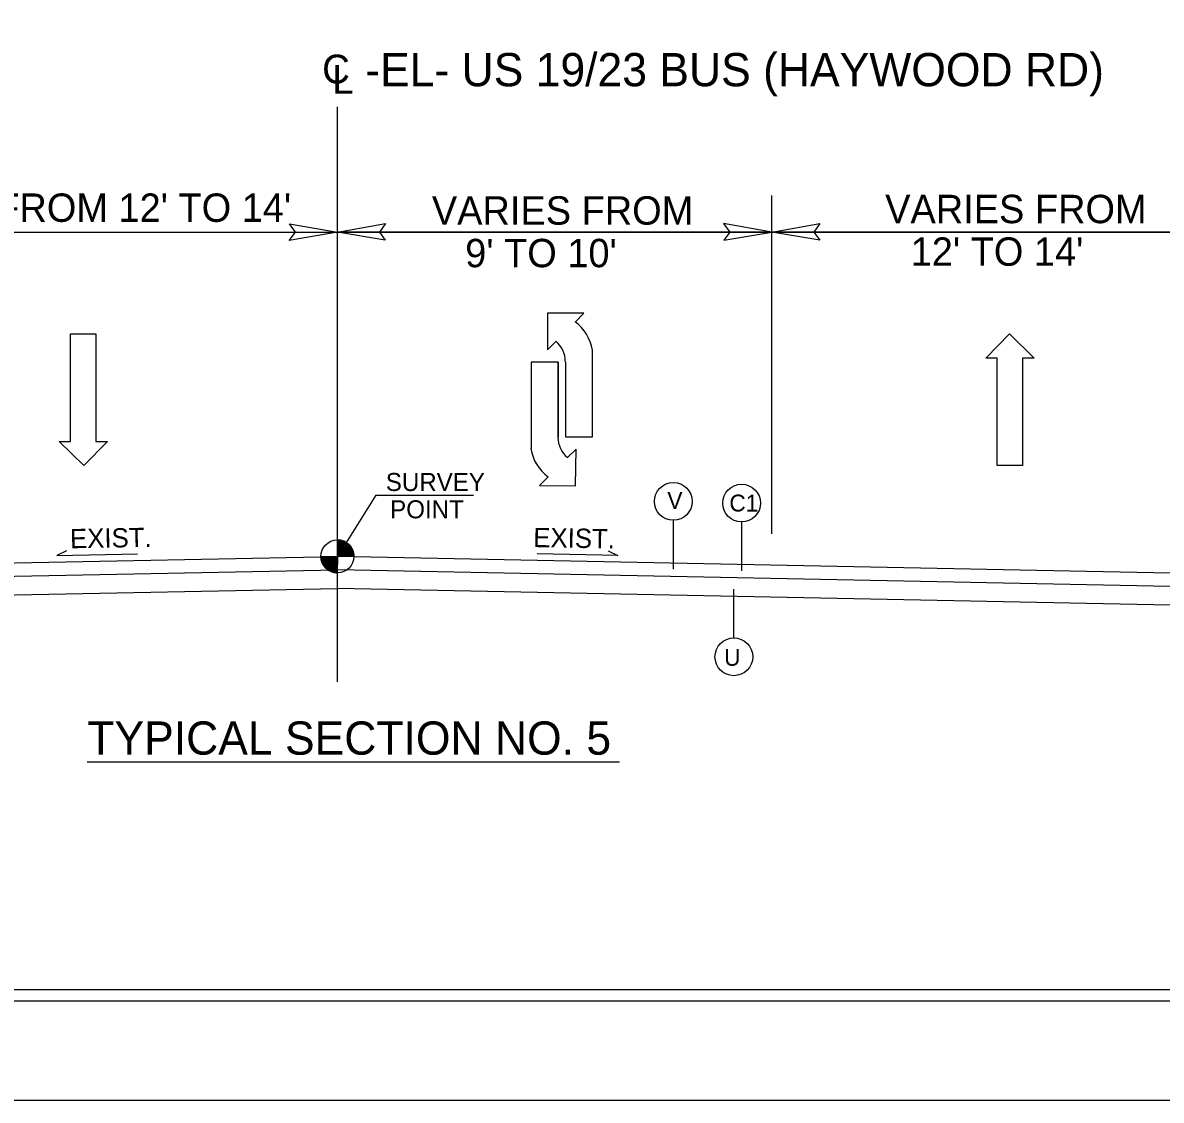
# Model space of a CAD drawing. Extents: x 1022283 to 1026986, y 174822 to 180471.
# Drawn here: x 1023630 to 1024272, y 177721 to 178329 of the extents above; entities that cross this region are included whole.
import ezdxf

# ---------------------------------------------------------------- set-up
doc = ezdxf.new("R2010")
doc.units = 0
for name, color, linetype in [('Default', 7, 'Continuous'), ('Prop Dimension', 7, 'Continuous'), ('Prop Lane Arrow CELL', 7, 'Continuous'), ('Prop Terminator CELL', 7, 'Continuous'), ('Sheet Cutting Line CELL', 7, 'Continuous'), ('Sheet Plot Border Inside CELL', 7, 'Continuous'), ('Sheet Plot Border Outside CELL', 7, 'Continuous'), ('Sheet Typical CELL', 7, 'Continuous'), ('Typical Berm Information CELL', 7, 'Continuous'), ('Typical Grade Point Symbol CELL', 7, 'Continuous'), ('Typical ID Circle CELL', 7, 'Continuous'), ('Typical Text Centerline CELL', 7, 'Continuous'), ('Typical Text Grade Point CELL', 7, 'Continuous'), ('Typical Text ID Circle CELL', 7, 'Continuous'), ('Typical Text Label CELL', 7, 'Continuous')]:
    doc.layers.add(name, color=color, linetype=linetype)

# ---------------------------------------------------------------- blocks, each defined once
blk = doc.blocks.new('Lane Arrow Through')
at = {"layer": 'Prop Lane Arrow CELL'}
for p, q in [((-3.15, 1.6), (-3.15, 3.1)), ((-3.15, 3.1), (0, 0)), ((-17.15, 1.6), (-3.15, 1.6)), ((-17.15, -1.7), (-17.15, 1.6)), ((0, 0), (-3.15, -3.2)), ((-3.15, -1.7), (-17.15, -1.7)), ((-3.15, -3.2), (-3.15, -1.7))]:
    blk.add_line(p, q, dxfattribs=at)

msp = doc.modelspace()

# ---------------------------------------------------------------- linework, layer by layer
at = {"layer": 'Default'}
for p, q in [((1024052.49, 178040.74), (1024052.49, 178231.56)), ((1023299.79, 178211), (1023807.5, 178211)), ((1023807.5, 178211), (1024315.21, 178211)), ((1024315.21, 178211), (1023807.5, 178211))]:
    msp.add_line(p, q, dxfattribs=at)
at = {"layer": 'Prop Dimension'}
for p, q in [((1023807.5, 178222.11), (1023807.5, 178281.56)), ((1023807.5, 177957.31), (1023807.5, 178222.11)), ((1023829.15, 178062.54), (1023807.5, 178028.1)), ((1023829.15, 178062.54), (1023807.5, 178028.1)), ((1023299.79, 178017.95), (1023807.5, 178028.1)), ((1023299.79, 178017.95), (1023807.5, 178028.1)), ((1024315.21, 178017.95), (1023807.5, 178028.1)), ((1024315.21, 178017.95), (1023807.5, 178028.1)), ((1023299.79, 178010.45), (1023807.5, 178020.6)), ((1023299.79, 178010.45), (1023807.5, 178020.6)), ((1024315.21, 178010.45), (1023807.5, 178020.6)), ((1024315.21, 178010.45), (1023807.5, 178020.6)), ((1023299.79, 177999.86), (1023807.5, 178010.02)), ((1024315.21, 177999.86), (1023807.5, 178010.02))]:
    msp.add_line(p, q, dxfattribs=at)
at = {"layer": 'Prop Lane Arrow CELL'}
for p, q in [((1023946.5, 178165.31), (1023925.95, 178165.31)), ((1023925.95, 178165.31), (1023925.95, 178144.53)), ((1023941.65, 178160.23), (1023946.5, 178165.31)), ((1023925.95, 178144.53), (1023930.8, 178149.38)), ((1023951.35, 178095.58), (1023951.35, 178144.3)), ((1023916.72, 178137.6), (1023916.72, 178088.88)), ((1023931.96, 178137.6), (1023916.72, 178137.6)), ((1023931.96, 178095.35), (1023931.96, 178137.6)), ((1023931.96, 178137.6), (1023931.96, 178095.35)), ((1023936.11, 178137.83), (1023936.11, 178095.58)), ((1023936.11, 178095.58), (1023951.35, 178095.58)), ((1023942.12, 178088.65), (1023937.27, 178083.8)), ((1023941.88, 178067.87), (1023942.12, 178088.65)), ((1023926.41, 178072.95), (1023921.57, 178068.1)), ((1023921.57, 178068.1), (1023941.88, 178067.87))]:
    msp.add_line(p, q, dxfattribs=at)
for centre, radius, start, end in [((1023927.32, 178140.7), 24.26, 8.67607, 53.98777), ((1023920.93, 178137.94), 15.12, 360, 49.65817), ((1023947, 178095.3), 15.12, 180, 229.65817), ((1023940.62, 178092.54), 24.26, 188.67607, 233.98777)]:
    msp.add_arc(centre, radius, start, end, dxfattribs=at)
at = {"layer": 'Prop Terminator CELL'}
for points in [[(1023780.5, 178215.65), (1023807.5, 178211), (1023780.35, 178206.2), (1023783.8, 178211)], [(1023834.5, 178206.35), (1023807.5, 178211), (1023834.65, 178215.8), (1023831.2, 178211)], [(1023834.5, 178206.35), (1023807.5, 178211), (1023834.65, 178215.8), (1023831.2, 178211)], [(1024025.49, 178206.35), (1024052.49, 178211), (1024025.34, 178215.8), (1024028.79, 178211)], [(1024079.49, 178206.35), (1024052.49, 178211), (1024079.64, 178215.8), (1024076.19, 178211)]]:
    msp.add_lwpolyline(points, close=True, dxfattribs=at)
at = {"layer": 'Sheet Cutting Line CELL'}
msp.add_line((1022283.22, 177721.48), (1026493.22, 177721.48), dxfattribs=at)
at = {"layer": 'Sheet Plot Border Inside CELL'}
msp.add_lwpolyline([(1026481.97, 180415.35), (1022315.72, 180415.35), (1022315.72, 177777.6), (1026481.97, 177777.6)], close=True, dxfattribs=at)
at = {"layer": 'Sheet Plot Border Outside CELL'}
msp.add_lwpolyline([(1026493.22, 180471.48), (1022283.22, 180471.48), (1022283.22, 177721.48), (1026493.22, 177721.48)], close=True, dxfattribs=at)
at = {"layer": 'Sheet Typical CELL'}
msp.add_lwpolyline([(1026450.72, 180408.98), (1022700.72, 180408.98), (1022700.72, 177783.98), (1026450.72, 177783.98)], close=True, dxfattribs=at)
at = {"layer": 'Typical Berm Information CELL'}
for p, q in [((1023654.85, 178031.31), (1023649.33, 178028.55)), ((1023649.33, 178028.55), (1023694.85, 178029.46)), ((1023965.68, 178028.55), (1023920.16, 178029.46)), ((1023960.16, 178031.31), (1023965.68, 178028.55))]:
    msp.add_line(p, q, dxfattribs=at)
at = {"layer": 'Typical Grade Point Symbol CELL'}
for p, q in [((1023807.5, 178028.1), (1023807.5, 178037.4)), ((1023807.5, 178028.1), (1023807.5, 178037.4)), ((1023798.21, 178028.1), (1023807.5, 178028.1)), ((1023798.21, 178028.1), (1023807.5, 178028.1)), ((1023807.48, 178018.81), (1023807.5, 178028.1)), ((1023807.5, 178028.1), (1023807.48, 178018.81)), ((1023807.48, 178018.81), (1023807.5, 178028.1)), ((1023807.5, 178028.1), (1023807.48, 178018.81)), ((1023816.8, 178028.1), (1023807.5, 178028.1)), ((1023816.8, 178028.1), (1023807.5, 178028.1))]:
    msp.add_line(p, q, dxfattribs=at)
for points in [[(1023807.59, 178037.4), (1023807.59, 178037.4), (1023807.59, 178028.1)], [(1023807.59, 178037.4), (1023807.59, 178037.4), (1023807.59, 178028.1)], [(1023807.77, 178037.4), (1023807.77, 178028.1)], [(1023807.77, 178037.4), (1023807.77, 178028.1)], [(1023807.96, 178037.38), (1023807.96, 178028.1)], [(1023807.96, 178037.38), (1023807.96, 178028.1)], [(1023808.14, 178037.38), (1023808.14, 178028.1)], [(1023808.14, 178037.38), (1023808.14, 178028.1)], [(1023808.33, 178037.36), (1023808.33, 178028.1)], [(1023808.33, 178037.36), (1023808.33, 178028.1)], [(1023808.52, 178037.34), (1023808.52, 178028.1)], [(1023808.52, 178037.34), (1023808.52, 178028.1)], [(1023808.7, 178037.32), (1023808.7, 178028.1)], [(1023808.7, 178037.32), (1023808.7, 178028.1)], [(1023808.89, 178037.29), (1023808.89, 178028.1)], [(1023808.89, 178037.29), (1023808.89, 178028.1)], [(1023809.07, 178037.27), (1023809.07, 178028.1)], [(1023809.07, 178037.27), (1023809.07, 178028.1)], [(1023809.26, 178037.23), (1023809.26, 178028.1)], [(1023809.26, 178037.23), (1023809.26, 178028.1)], [(1023809.45, 178037.19), (1023809.45, 178028.1)], [(1023809.45, 178037.19), (1023809.45, 178028.1)], [(1023809.63, 178037.15), (1023809.63, 178028.1)], [(1023809.63, 178037.15), (1023809.63, 178028.1)], [(1023809.82, 178037.11), (1023809.82, 178028.1)], [(1023809.82, 178037.11), (1023809.82, 178028.1)], [(1023810, 178037.05), (1023810, 178028.1)], [(1023810, 178037.05), (1023810, 178028.1)], [(1023810.19, 178037.01), (1023810.19, 178028.1)], [(1023810.19, 178037.01), (1023810.19, 178028.1)], [(1023810.38, 178036.94), (1023810.38, 178028.1)], [(1023810.38, 178036.94), (1023810.38, 178028.1)], [(1023810.56, 178036.88), (1023810.56, 178028.1)], [(1023810.56, 178036.88), (1023810.56, 178028.1)], [(1023810.75, 178036.82), (1023810.75, 178028.1)], [(1023810.75, 178036.82), (1023810.75, 178028.1)], [(1023810.93, 178036.74), (1023810.93, 178028.1)], [(1023810.93, 178036.74), (1023810.93, 178028.1)], [(1023811.12, 178036.65), (1023811.12, 178028.1)], [(1023811.12, 178036.65), (1023811.12, 178028.1)], [(1023811.31, 178036.57), (1023811.31, 178028.1)], [(1023811.31, 178036.57), (1023811.31, 178028.1)], [(1023811.49, 178036.49), (1023811.49, 178028.1)], [(1023811.49, 178036.49), (1023811.49, 178028.1)], [(1023811.68, 178036.41), (1023811.68, 178028.1)], [(1023811.68, 178036.41), (1023811.68, 178028.1)], [(1023811.86, 178036.3), (1023811.86, 178028.1)], [(1023811.86, 178036.3), (1023811.86, 178028.1)], [(1023812.05, 178036.2), (1023812.05, 178028.1)], [(1023812.05, 178036.2), (1023812.05, 178028.1)], [(1023812.23, 178036.1), (1023812.23, 178028.1)], [(1023812.23, 178036.1), (1023812.23, 178028.1)], [(1023812.42, 178035.99), (1023812.42, 178028.1)], [(1023812.42, 178035.99), (1023812.42, 178028.1)], [(1023812.61, 178035.87), (1023812.61, 178028.1)], [(1023812.61, 178035.87), (1023812.61, 178028.1)], [(1023812.79, 178035.75), (1023812.79, 178028.1)], [(1023812.79, 178035.75), (1023812.79, 178028.1)], [(1023812.98, 178035.6), (1023812.98, 178028.1)], [(1023812.98, 178035.6), (1023812.98, 178028.1)], [(1023813.16, 178035.48), (1023813.16, 178028.1)], [(1023813.16, 178035.48), (1023813.16, 178028.1)], [(1023813.35, 178035.33), (1023813.35, 178028.1)], [(1023813.35, 178035.33), (1023813.35, 178028.1)], [(1023813.54, 178035.17), (1023813.54, 178028.1)], [(1023813.54, 178035.17), (1023813.54, 178028.1)], [(1023813.72, 178035), (1023813.72, 178028.1)], [(1023813.72, 178035), (1023813.72, 178028.1)], [(1023813.91, 178034.84), (1023813.91, 178028.1)], [(1023813.91, 178034.84), (1023813.91, 178028.1)], [(1023814.09, 178034.65), (1023814.09, 178028.1)], [(1023814.09, 178034.65), (1023814.09, 178028.1)], [(1023814.28, 178034.46), (1023814.28, 178028.1)], [(1023814.28, 178034.46), (1023814.28, 178028.1)], [(1023814.47, 178034.26), (1023814.47, 178028.1)], [(1023814.47, 178034.26), (1023814.47, 178028.1)], [(1023814.65, 178034.03), (1023814.65, 178028.1)], [(1023814.65, 178034.03), (1023814.65, 178028.1)], [(1023814.84, 178033.8), (1023814.84, 178028.1)], [(1023814.84, 178033.8), (1023814.84, 178028.1)], [(1023815.02, 178033.56), (1023815.02, 178028.1)], [(1023815.02, 178033.56), (1023815.02, 178028.1)], [(1023815.21, 178033.29), (1023815.21, 178028.1)], [(1023815.21, 178033.29), (1023815.21, 178028.1)], [(1023815.4, 178033), (1023815.4, 178028.1)], [(1023815.4, 178033), (1023815.4, 178028.1)], [(1023815.58, 178032.69), (1023815.58, 178028.1)], [(1023815.58, 178032.69), (1023815.58, 178028.1)], [(1023815.77, 178032.36), (1023815.77, 178028.1)], [(1023815.77, 178032.36), (1023815.77, 178028.1)], [(1023815.95, 178031.97), (1023815.95, 178028.1)], [(1023815.95, 178031.97), (1023815.95, 178028.1)], [(1023816.14, 178031.53), (1023816.14, 178028.1)], [(1023816.14, 178031.53), (1023816.14, 178028.1)], [(1023798.25, 178028.1), (1023798.25, 178027.09)], [(1023798.25, 178028.1), (1023798.25, 178027.09)], [(1023798.44, 178028.1), (1023798.44, 178026)], [(1023798.44, 178028.1), (1023798.44, 178026)], [(1023798.62, 178028.1), (1023798.62, 178025.33)], [(1023798.62, 178028.1), (1023798.62, 178025.33)], [(1023798.81, 178028.1), (1023798.81, 178024.78)], [(1023798.81, 178028.1), (1023798.81, 178024.78)], [(1023798.99, 178028.1), (1023798.99, 178024.34)], [(1023798.99, 178028.1), (1023798.99, 178024.34)], [(1023799.18, 178028.1), (1023799.18, 178023.95)], [(1023799.18, 178028.1), (1023799.18, 178023.95)], [(1023799.37, 178028.1), (1023799.37, 178023.6)], [(1023799.37, 178028.1), (1023799.37, 178023.6)], [(1023799.55, 178028.1), (1023799.55, 178023.27)], [(1023799.55, 178028.1), (1023799.55, 178023.27)], [(1023799.74, 178028.1), (1023799.74, 178022.98)], [(1023799.74, 178028.1), (1023799.74, 178022.98)], [(1023799.92, 178028.1), (1023799.92, 178022.71)], [(1023799.92, 178028.1), (1023799.92, 178022.71)], [(1023800.11, 178028.1), (1023800.11, 178022.46)], [(1023800.11, 178028.1), (1023800.11, 178022.46)], [(1023800.3, 178028.1), (1023800.3, 178022.24)], [(1023800.3, 178028.1), (1023800.3, 178022.24)], [(1023800.48, 178028.1), (1023800.48, 178022.01)], [(1023800.48, 178028.1), (1023800.48, 178022.01)], [(1023800.67, 178028.1), (1023800.67, 178021.8)], [(1023800.67, 178028.1), (1023800.67, 178021.8)], [(1023800.85, 178028.1), (1023800.85, 178021.6)], [(1023800.85, 178028.1), (1023800.85, 178021.6)], [(1023801.04, 178028.1), (1023801.04, 178021.41)], [(1023801.04, 178028.1), (1023801.04, 178021.41)], [(1023801.23, 178028.1), (1023801.23, 178021.24)], [(1023801.23, 178028.1), (1023801.23, 178021.24)], [(1023801.41, 178028.1), (1023801.41, 178021.08)], [(1023801.41, 178028.1), (1023801.41, 178021.08)], [(1023801.6, 178028.1), (1023801.6, 178020.92)], [(1023801.6, 178028.1), (1023801.6, 178020.92)], [(1023801.78, 178028.1), (1023801.78, 178020.77)], [(1023801.78, 178028.1), (1023801.78, 178020.77)], [(1023801.97, 178028.1), (1023801.97, 178020.63)], [(1023801.97, 178028.1), (1023801.97, 178020.63)], [(1023802.15, 178028.1), (1023802.15, 178020.5)], [(1023802.15, 178028.1), (1023802.15, 178020.5)], [(1023802.34, 178028.1), (1023802.34, 178020.38)], [(1023802.34, 178028.1), (1023802.34, 178020.38)], [(1023802.53, 178028.1), (1023802.53, 178020.25)], [(1023802.53, 178028.1), (1023802.53, 178020.25)], [(1023802.71, 178028.1), (1023802.71, 178020.13)], [(1023802.71, 178028.1), (1023802.71, 178020.13)], [(1023802.9, 178028.1), (1023802.9, 178020.03)], [(1023802.9, 178028.1), (1023802.9, 178020.03)], [(1023803.08, 178028.1), (1023803.08, 178019.92)], [(1023803.08, 178028.1), (1023803.08, 178019.92)], [(1023803.27, 178028.1), (1023803.27, 178019.82)], [(1023803.27, 178028.1), (1023803.27, 178019.82)], [(1023803.46, 178028.1), (1023803.46, 178019.74)], [(1023803.46, 178028.1), (1023803.46, 178019.74)], [(1023803.64, 178028.1), (1023803.64, 178019.65)], [(1023803.64, 178028.1), (1023803.64, 178019.65)], [(1023803.83, 178028.1), (1023803.83, 178019.57)], [(1023803.83, 178028.1), (1023803.83, 178019.57)], [(1023804.01, 178028.1), (1023804.01, 178019.49)], [(1023804.01, 178028.1), (1023804.01, 178019.49)], [(1023804.2, 178028.1), (1023804.2, 178019.41)], [(1023804.2, 178028.1), (1023804.2, 178019.41)], [(1023804.39, 178028.1), (1023804.39, 178019.34)], [(1023804.39, 178028.1), (1023804.39, 178019.34)], [(1023804.57, 178028.1), (1023804.57, 178019.28)], [(1023804.57, 178028.1), (1023804.57, 178019.28)], [(1023804.76, 178028.1), (1023804.76, 178019.22)], [(1023804.76, 178028.1), (1023804.76, 178019.22)], [(1023804.94, 178028.1), (1023804.94, 178019.18)], [(1023804.94, 178028.1), (1023804.94, 178019.18)], [(1023805.13, 178028.1), (1023805.13, 178019.12)], [(1023805.13, 178028.1), (1023805.13, 178019.12)], [(1023805.32, 178028.1), (1023805.32, 178019.08)], [(1023805.32, 178028.1), (1023805.32, 178019.08)], [(1023805.5, 178028.1), (1023805.5, 178019.03)], [(1023805.5, 178028.1), (1023805.5, 178019.03)], [(1023805.69, 178028.1), (1023805.69, 178018.99)], [(1023805.69, 178028.1), (1023805.69, 178018.99)], [(1023805.87, 178028.1), (1023805.87, 178018.95)], [(1023805.87, 178028.1), (1023805.87, 178018.95)], [(1023806.06, 178028.1), (1023806.06, 178018.93)], [(1023806.06, 178028.1), (1023806.06, 178018.93)], [(1023806.24, 178028.1), (1023806.24, 178018.89)], [(1023806.24, 178028.1), (1023806.24, 178018.89)], [(1023806.43, 178028.1), (1023806.43, 178018.87)], [(1023806.43, 178028.1), (1023806.43, 178018.87)], [(1023806.62, 178028.1), (1023806.62, 178018.85)], [(1023806.62, 178028.1), (1023806.62, 178018.85)], [(1023806.8, 178028.1), (1023806.8, 178018.83)], [(1023806.8, 178028.1), (1023806.8, 178018.83)], [(1023806.99, 178028.1), (1023806.99, 178018.83)], [(1023806.99, 178028.1), (1023806.99, 178018.83)], [(1023807.17, 178028.1), (1023807.17, 178018.81)], [(1023807.17, 178028.1), (1023807.17, 178018.81)], [(1023807.36, 178028.1), (1023807.36, 178018.81), (1023807.36, 178018.81)], [(1023807.36, 178028.1), (1023807.36, 178018.81), (1023807.36, 178018.81)], [(1023816.32, 178031.01), (1023816.32, 178028.1)], [(1023816.32, 178031.01), (1023816.32, 178028.1)], [(1023816.51, 178030.37), (1023816.51, 178028.1)], [(1023816.51, 178030.37), (1023816.51, 178028.1)], [(1023816.7, 178029.43), (1023816.7, 178028.1)], [(1023816.7, 178029.43), (1023816.7, 178028.1)]]:
    msp.add_lwpolyline(points, dxfattribs=at)
msp.add_circle((1023807.49, 178028.11), 9.3, dxfattribs=at)
msp.add_circle((1023807.49, 178028.11), 9.3, dxfattribs=at)
for start, end in [(359.99048, 89.99048), (359.99048, 89.99048), (179.99048, 269.99048), (179.99048, 269.99048)]:
    msp.add_arc((1023807.49, 178028.11), 9.3, start, end, dxfattribs=at)
at = {"layer": 'Typical ID Circle CELL'}
for p, q in [((1023996.95, 178048.46), (1023996.95, 178020.93)), ((1024035.48, 178047.5), (1024035.48, 178019.97)), ((1024031.08, 177982.13), (1024031.08, 178009.66))]:
    msp.add_line(p, q, dxfattribs=at)
for centre in [(1023996.95, 178059.11), (1024035.48, 178058.15), (1024031.08, 177971.48)]:
    msp.add_circle(centre, 10.65, dxfattribs=at)
at = {"layer": 'Typical Text Grade Point CELL'}
msp.add_line((1023829.15, 178062.54), (1023884.26, 178062.54), dxfattribs=at)
at = {"layer": 'Typical Text Label CELL'}
msp.add_line((1023666.49, 177912.3), (1023966.6, 177912.3), dxfattribs=at)

# ---------------------------------------------------------------- block references
at = {"layer": 'Prop Lane Arrow CELL', "xscale": 4.329849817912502}
for p, yscale, rotation in [((1023664.46, 178079.31), 4.3298498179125, -89.99999999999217), ((1024186.56, 178153.57), 4.329849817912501, 90.00000000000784)]:
    msp.add_blockref('Lane Arrow Through', p, dxfattribs=dict(at, yscale=yscale, rotation=rotation))

# ---------------------------------------------------------------- texts
at = {"layer": 'Prop Dimension'}
for s, height, p in [('-EL- US 19/23 BUS (HAYWOOD RD) ', 18.75, (1023823.22, 178293.16)), ("VARIES FROM 12' TO 14'", 16, (1023530.73, 178216.72)), ('VARIES FROM', 16, (1023860.8, 178215.14)), ('VARIES FROM ', 16, (1024116.42, 178215.97)), ("9' TO 10'", 16, (1023879.6, 178191.14)), ("12' TO 14'", 16, (1024130.81, 178191.97))]:
    msp.add_text(s, height=height, dxfattribs=at).set_placement(p)
at = {"layer": 'Typical Berm Information CELL'}
for rotation, p in [(0.99274, (1023656.82, 178032.66)), (359.00726, (1023917.9, 178033.35))]:
    msp.add_text('EXIST.', height=10.873, rotation=rotation, dxfattribs=at).set_placement(p)
at = {"layer": 'Typical Text Centerline CELL'}
msp.add_text('C', height=16.22, dxfattribs=at).set_placement((1023798.92, 178294.77))
msp.add_text('L', height=16.22, rotation=359.9469, dxfattribs=at).set_placement((1023804.58, 178288.96))
at = {"layer": 'Typical Text Grade Point CELL'}
for s, p in [('SURVEY', (1023834.82, 178064.97)), ('POINT', (1023837.27, 178049.57))]:
    msp.add_text(s, height=10.163, dxfattribs=at).set_placement(p)
at = {"layer": 'Typical Text ID Circle CELL'}
for s, height, p in [('V', 9.53, (1023993.6, 178054.81)), ('C1', 9.534, (1024028.59, 178053.41)), ('U', 9.53, (1024025.63, 177966.42))]:
    msp.add_text(s, height=height, dxfattribs=at).set_placement(p)
at = {"layer": 'Typical Text Label CELL'}
msp.add_text('TYPICAL SECTION NO. 5', height=18.75, dxfattribs=at).set_placement((1023666.49, 177916.3))

doc.saveas('drawing.dxf')
